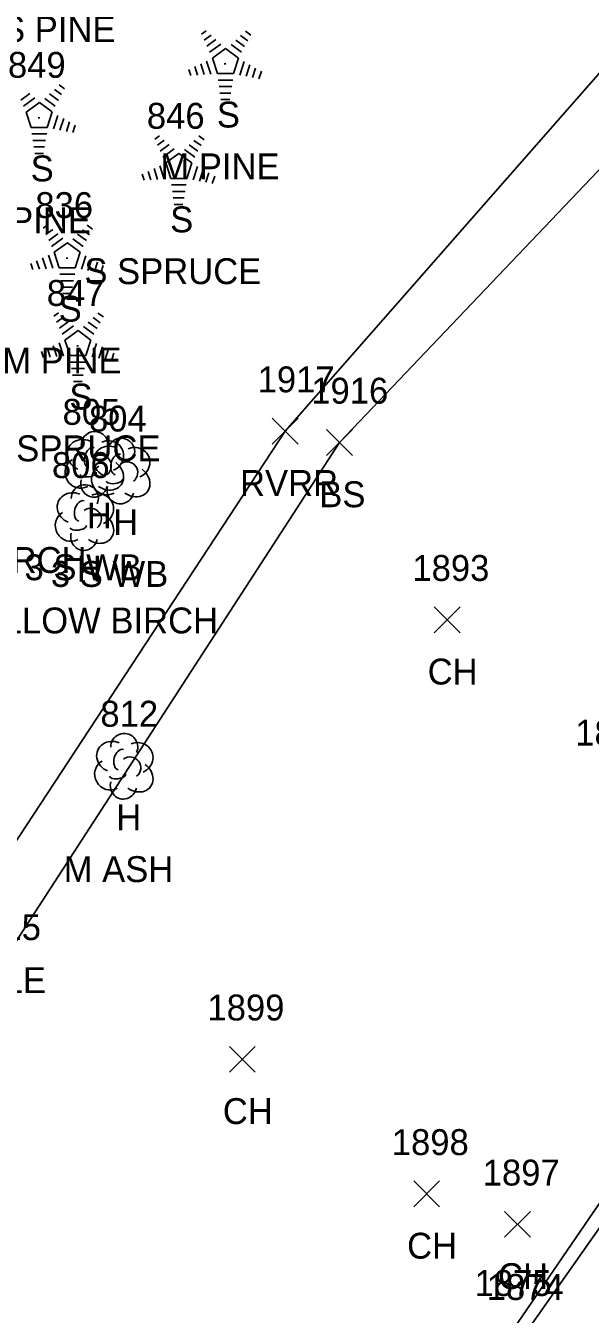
# Model space of a CAD drawing. Extents: x 1545627 to 1546562, y 571176 to 576667.
# Drawn here: x 1546167.5 to 1546211.1, y 572214.6 to 572314.1 of the extents above; entities that cross this region are included whole.
import ezdxf

# ---------------------------------------------------------------- set-up
doc = ezdxf.new("R2010")
doc.units = 0
for name, color, linetype in [('L_A', 7, 'Continuous'), ('L_C', 7, 'Continuous'), ('L_I', 7, 'Continuous'), ('L_TIC', 7, 'Continuous'), ('LAWE', 7, 'Continuous'), ('LELB', 7, 'Continuous'), ('LTC', 7, 'Continuous'), ('LTD', 7, 'Continuous')]:
    doc.layers.add(name, color=color, linetype=linetype)

msp = doc.modelspace()

# ---------------------------------------------------------------- linework, layer by layer
at = {"layer": 'L_TIC'}
for points in [[(1546186.565, 572281.786), (1546188.565, 572283.786)], [(1546188.565, 572281.786), (1546186.565, 572283.786)], [(1546190.763, 572280.913), (1546192.763, 572282.913)], [(1546192.763, 572280.913), (1546190.763, 572282.913)], [(1546199.088, 572267.221), (1546201.088, 572269.221)], [(1546201.088, 572267.221), (1546199.088, 572269.221)], [(1546183.26, 572233.275), (1546185.26, 572235.275)], [(1546185.26, 572233.275), (1546183.26, 572235.275)], [(1546197.499, 572222.88), (1546199.499, 572224.88)], [(1546199.499, 572222.88), (1546197.499, 572224.88)], [(1546204.526, 572220.528), (1546206.526, 572222.528)], [(1546206.526, 572220.528), (1546204.526, 572222.528)]]:
    msp.add_lwpolyline(points, dxfattribs=at)
at = {"layer": 'LAWE'}
for points in [[(1546079.438, 571966.947), (1546077.788, 571985.488), (1546075.176, 572034.738), (1546072.514, 572073.367), (1546072.957, 572091.545), (1546079.326, 572109.636), (1546089.965, 572133.875), (1546098.205, 572146.168), (1546103.269, 572146.803), (1546106.386, 572149.622), (1546130.143, 572181.263), (1546136.759, 572192.153), (1546140.729, 572200.768), (1546161.621, 572243.317), (1546187.565, 572282.786), (1546232.645, 572334.154), (1546255.297, 572360.235), (1546268.959, 572391.116)], [(1546121.265, 571957.172), (1546118.803, 571996.677), (1546114.937, 572038.101), (1546108, 572065.636), (1546104.767, 572084.584), (1546111.687, 572095.842), (1546118.703, 572113.935), (1546133.848, 572134.836), (1546145.167, 572135.646), (1546153.927, 572139.019), (1546169.651, 572160.036), (1546189.008, 572163.697), (1546206.714, 572193.958), (1546205.832, 572212.69), (1546216.066, 572227.226), (1546228.024, 572235.176), (1546234.868, 572265.766), (1546262.797, 572295.702), (1546275.487, 572309.557), (1546290.065, 572324.25)]]:
    msp.add_lwpolyline(points, dxfattribs=at)
at = {"layer": 'LELB'}
for points in [[(1546140.457, 572188.687), (1546144.086, 572197.302), (1546164.869, 572240.482), (1546191.763, 572281.913), (1546238.283, 572330.782), (1546258.38, 572354.309), (1546270.264, 572391.299)], [(1546138.465, 572142.662), (1546151.843, 572140.861), (1546169.324, 572161.725), (1546185.772, 572170.699), (1546202.895, 572194.936), (1546204.894, 572212.997), (1546215.164, 572227.989), (1546230.472, 572267.575), (1546260.052, 572296.387), (1546273.8, 572312.974), (1546290.068, 572327.618), (1546314.576, 572291.02)]]:
    msp.add_lwpolyline(points, dxfattribs=at)
at = {"layer": 'LTC'}
for p, q in [((1546181.096, 572313.446), (1546181.45, 572313.703)), ((1546184.494, 572313.686), (1546184.913, 572313.382)), ((1546181.305, 572312.98), (1546181.835, 572313.364)), ((1546181.515, 572312.514), (1546182.219, 572313.026)), ((1546181.725, 572312.049), (1546182.603, 572312.687)), ((1546183.381, 572312.641), (1546184.19, 572312.052)), ((1546183.752, 572312.989), (1546184.431, 572312.496)), ((1546184.123, 572313.338), (1546184.672, 572312.939)), ((1546181.949, 572311.594), (1546182.961, 572312.328)), ((1546181.949, 572311.594), (1546182.336, 572310.4)), ((1546182.961, 572312.328), (1546183.958, 572311.603)), ((1546183.958, 572311.603), (1546183.567, 572310.4)), ((1546180.128, 572310.725), (1546180.28, 572310.257)), ((1546180.584, 572310.942), (1546180.795, 572310.29)), ((1546181.039, 572311.158), (1546181.31, 572310.323)), ((1546181.495, 572311.374), (1546181.825, 572310.355)), ((1546184.395, 572311.332), (1546184.057, 572310.293)), ((1546184.84, 572311.082), (1546184.552, 572310.197)), ((1546185.285, 572310.832), (1546185.047, 572310.102)), ((1546185.729, 572310.582), (1546185.542, 572310.007)), ((1546170.106, 572309.526), (1546170.525, 572309.222)), ((1546183.567, 572310.4), (1546182.336, 572310.4)), ((1546183.528, 572309.9), (1546182.384, 572309.9)), ((1546167.127, 572308.354), (1546167.831, 572308.866)), ((1546167.337, 572307.889), (1546168.215, 572308.527)), ((1546169.364, 572308.829), (1546170.043, 572308.336)), ((1546169.735, 572309.178), (1546170.285, 572308.779)), ((1546183.445, 572309.4), (1546182.456, 572309.4)), ((1546183.361, 572308.9), (1546182.529, 572308.9)), ((1546167.561, 572307.434), (1546168.573, 572308.168)), ((1546168.573, 572308.168), (1546169.57, 572307.443)), ((1546168.993, 572308.481), (1546169.802, 572307.892)), ((1546183.277, 572308.4), (1546182.602, 572308.4)), ((1546167.561, 572307.434), (1546167.948, 572306.24)), ((1546169.57, 572307.443), (1546169.179, 572306.24)), ((1546170.007, 572307.172), (1546169.67, 572306.133)), ((1546170.452, 572306.922), (1546170.165, 572306.037)), ((1546170.897, 572306.672), (1546170.66, 572305.942)), ((1546169.179, 572306.24), (1546167.948, 572306.24)), ((1546169.14, 572305.74), (1546167.996, 572305.74)), ((1546171.341, 572306.422), (1546171.154, 572305.847)), ((1546177.489, 572305.35), (1546177.843, 572305.608)), ((1546180.887, 572305.591), (1546181.306, 572305.286)), ((1546169.057, 572305.24), (1546168.068, 572305.24)), ((1546168.973, 572304.74), (1546168.141, 572304.74)), ((1546177.698, 572304.885), (1546178.227, 572305.269)), ((1546177.908, 572304.419), (1546178.612, 572304.93)), ((1546178.117, 572303.953), (1546178.996, 572304.591)), ((1546179.774, 572304.546), (1546180.583, 572303.957)), ((1546180.145, 572304.894), (1546180.824, 572304.4)), ((1546180.516, 572305.242), (1546181.065, 572304.843)), ((1546168.889, 572304.24), (1546168.214, 572304.24)), ((1546178.342, 572303.498), (1546179.354, 572304.233)), ((1546179.354, 572304.233), (1546180.351, 572303.508)), ((1546176.521, 572302.63), (1546176.673, 572302.162)), ((1546176.977, 572302.846), (1546177.188, 572302.195)), ((1546177.432, 572303.063), (1546177.703, 572302.227)), ((1546177.887, 572303.279), (1546178.218, 572302.26)), ((1546178.342, 572303.498), (1546178.729, 572302.305)), ((1546180.351, 572303.508), (1546179.959, 572302.305)), ((1546180.788, 572303.237), (1546180.45, 572302.197)), ((1546181.233, 572302.987), (1546180.945, 572302.102)), ((1546181.677, 572302.737), (1546181.44, 572302.007)), ((1546179.959, 572302.305), (1546178.729, 572302.305)), ((1546179.921, 572301.805), (1546178.777, 572301.805)), ((1546182.122, 572302.486), (1546181.935, 572301.912)), ((1546179.837, 572301.305), (1546178.849, 572301.305)), ((1546179.754, 572300.805), (1546178.922, 572300.805)), ((1546179.67, 572300.305), (1546178.995, 572300.305)), ((1546168.873, 572298.453), (1546169.227, 572298.711)), ((1546172.271, 572298.694), (1546172.69, 572298.389)), ((1546169.082, 572297.988), (1546169.611, 572298.372)), ((1546169.292, 572297.522), (1546169.995, 572298.033)), ((1546169.501, 572297.056), (1546170.38, 572297.694)), ((1546171.157, 572297.649), (1546171.967, 572297.06)), ((1546171.529, 572297.997), (1546172.208, 572297.503)), ((1546171.9, 572298.345), (1546172.449, 572297.946)), ((1546169.726, 572296.601), (1546170.737, 572297.336)), ((1546169.726, 572296.601), (1546170.113, 572295.408)), ((1546170.737, 572297.336), (1546171.735, 572296.611)), ((1546171.735, 572296.611), (1546171.343, 572295.408)), ((1546167.905, 572295.732), (1546168.057, 572295.264)), ((1546168.36, 572295.949), (1546168.572, 572295.297)), ((1546168.816, 572296.166), (1546169.087, 572295.33)), ((1546169.271, 572296.382), (1546169.602, 572295.363)), ((1546172.172, 572296.34), (1546171.834, 572295.3)), ((1546172.617, 572296.089), (1546172.329, 572295.205)), ((1546173.061, 572295.839), (1546172.824, 572295.11)), ((1546173.505, 572295.589), (1546173.319, 572295.015)), ((1546171.343, 572295.408), (1546170.113, 572295.408)), ((1546171.305, 572294.908), (1546170.16, 572294.908)), ((1546171.221, 572294.408), (1546170.233, 572294.408)), ((1546171.137, 572293.908), (1546170.306, 572293.908)), ((1546171.054, 572293.408), (1546170.379, 572293.408)), ((1546169.699, 572291.669), (1546170.053, 572291.927)), ((1546173.097, 572291.91), (1546173.516, 572291.605)), ((1546169.908, 572291.204), (1546170.437, 572291.588)), ((1546170.118, 572290.738), (1546170.822, 572291.249)), ((1546170.327, 572290.272), (1546171.206, 572290.91)), ((1546171.984, 572290.865), (1546172.793, 572290.276)), ((1546172.355, 572291.213), (1546173.034, 572290.719)), ((1546172.726, 572291.562), (1546173.275, 572291.162)), ((1546170.552, 572289.817), (1546171.564, 572290.552)), ((1546170.552, 572289.817), (1546170.939, 572288.624)), ((1546171.564, 572290.552), (1546172.561, 572289.827)), ((1546172.561, 572289.827), (1546172.17, 572288.624)), ((1546168.731, 572288.949), (1546168.883, 572288.481)), ((1546169.187, 572289.165), (1546169.398, 572288.514)), ((1546169.642, 572289.382), (1546169.913, 572288.547)), ((1546170.097, 572289.598), (1546170.428, 572288.579)), ((1546172.17, 572288.624), (1546170.939, 572288.624)), ((1546172.998, 572289.556), (1546172.66, 572288.517)), ((1546173.443, 572289.306), (1546173.155, 572288.421)), ((1546173.887, 572289.056), (1546173.65, 572288.326)), ((1546174.332, 572288.805), (1546174.145, 572288.231)), ((1546172.131, 572288.124), (1546170.987, 572288.124)), ((1546172.047, 572287.624), (1546171.059, 572287.624)), ((1546171.964, 572287.124), (1546171.132, 572287.124)), ((1546171.88, 572286.624), (1546171.205, 572286.624))]:
    msp.add_line(p, q, dxfattribs=at)
at = {"layer": 'LTD'}
for p, q in [((1546172.805, 572280.277), (1546172.805, 572280.277)), ((1546172.805, 572280.277), (1546172.805, 572280.277)), ((1546174.843, 572279.759), (1546174.843, 572279.759)), ((1546174.843, 572279.759), (1546174.843, 572279.759)), ((1546172.037, 572276.167), (1546172.037, 572276.167)), ((1546172.037, 572276.167), (1546172.037, 572276.167)), ((1546175.082, 572256.963), (1546175.082, 572256.963)), ((1546175.082, 572256.963), (1546175.082, 572256.963))]:
    msp.add_line(p, q, dxfattribs=at)
for centre in [(1546172.852, 572281.711), (1546174.89, 572281.193), (1546172.084, 572277.601), (1546175.129, 572258.397)]:
    msp.add_arc(centre, 1.047, 335.52715, 180.95627, dxfattribs=at)
for centre, major_axis, ratio, start_param, end_param in [((1546172.013, 572280.943), (1.21, -0.512), 0.895232, 1.570796, 4.712389), ((1546174.051, 572280.426), (1.21, -0.512), 0.895232, 1.570796, 4.712389), ((1546173.847, 572280.86), (-1.141, -0.483), 0.949671, 1.570796, 4.712389), ((1546175.885, 572280.343), (-1.141, -0.483), 0.949671, 1.570796, 4.712389), ((1546172.597, 572280.735), (-0.208, -0.792), 0.645439, 3.141593, 6.283185), ((1546173.305, 572280.11), (-0.5, 0.667), 0.989748, 3.141593, 6.283185), ((1546174.635, 572280.218), (-0.208, -0.792), 0.645439, 3.141593, 6.283185), ((1546171.722, 572279.568), (0.584, -1.042), 0.959034, 3.141593, 6.283185), ((1546173.76, 572279.051), (0.584, -1.042), 0.959034, 3.141593, 6.283185), ((1546173.805, 572279.443), (-1.09, 0.792), 0.841452, 1.570796, 4.712389), ((1546175.343, 572279.593), (-0.5, 0.667), 0.989748, 3.141593, 6.283185), ((1546175.843, 572278.926), (-1.09, 0.792), 0.841452, 1.570796, 4.712389), ((1546172.806, 572278.777), (0.265, 1.061), 0.942809, 1.570796, 4.712389), ((1546172.347, 572279.526), (-0.625, -0.083), 0.423636, 0, 3.141593), ((1546174.385, 572279.009), (-0.625, -0.083), 0.423636, 0, 3.141593), ((1546171.245, 572276.834), (1.21, -0.512), 0.895232, 1.570796, 4.712389), ((1546173.078, 572276.751), (-1.141, -0.483), 0.949671, 1.570796, 4.712389), ((1546174.843, 572278.26), (0.265, 1.061), 0.942809, 1.570796, 4.712389), ((1546171.828, 572276.625), (-0.208, -0.792), 0.645439, 3.141593, 6.283185), ((1546172.537, 572276), (-0.5, 0.667), 0.989748, 3.141593, 6.283185), ((1546170.954, 572275.459), (0.584, -1.042), 0.959034, 3.141593, 6.283185), ((1546173.037, 572275.334), (-1.09, 0.792), 0.841452, 1.570796, 4.712389), ((1546172.037, 572274.667), (0.265, 1.061), 0.942809, 1.570796, 4.712389), ((1546171.579, 572275.417), (-0.625, -0.083), 0.423636, 0, 3.141593), ((1546174.29, 572257.63), (1.21, -0.512), 0.895232, 1.570796, 4.712389), ((1546176.124, 572257.547), (-1.141, -0.483), 0.949671, 1.570796, 4.712389), ((1546174.874, 572257.421), (-0.208, -0.792), 0.645439, 3.141593, 6.283185), ((1546173.999, 572256.255), (0.584, -1.042), 0.959034, 3.141593, 6.283185), ((1546175.582, 572256.797), (-0.5, 0.667), 0.989748, 3.141593, 6.283185), ((1546176.082, 572256.13), (-1.09, 0.792), 0.841452, 1.570796, 4.712389), ((1546174.624, 572256.213), (-0.625, -0.083), 0.423636, 0, 3.141593), ((1546175.082, 572255.463), (0.265, 1.061), 0.942809, 1.570796, 4.712389)]:
    msp.add_ellipse(centre, major_axis=major_axis, ratio=ratio, start_param=start_param, end_param=end_param, dxfattribs=at)

# ---------------------------------------------------------------- texts
at = {"layer": 'L_A'}
for s, p in [('S', (1546182.286, 572306.238)), ('S', (1546167.899, 572302.078)), ('S', (1546178.679, 572298.142)), ('S', (1546170.063, 572291.245)), ('S', (1546170.889, 572284.461)), ('RVRR', (1546184.077, 572277.786)), ('BS', (1546190.204, 572276.913)), ('H', (1546172.238, 572275.277)), ('H', (1546174.276, 572274.759)), ('H', (1546171.47, 572271.167)), ('CH', (1546198.577, 572263.221)), ('H', (1546174.515, 572251.963)), ('CH', (1546182.748, 572229.275)), ('CH', (1546196.987, 572218.88)), ('CH', (1546204.014, 572216.528))]:
    msp.add_text(s, height=2, dxfattribs=at).set_placement(p)
at = {"layer": 'L_C'}
for s, p in [('S PINE', (1546165.686, 572312.832)), ('M PINE', (1546177.924, 572302.238)), ('S PINE', (1546163.788, 572298.078)), ('S SPRUCE', (1546172.049, 572294.142)), ('M PINE', (1546165.701, 572287.245)), ('S SPRUCE', (1546164.259, 572280.461)), ('S YELLOW BIRCH', (1546149.482, 572271.837)), ('3 S WB', (1546167.427, 572271.277)), ('3 S WB', (1546169.465, 572270.759)), ('S YELLOW BIRCH', (1546159.643, 572267.167)), ('M ASH', (1546170.452, 572247.963)), ('3 S MAPLE', (1546155.259, 572239.386))]:
    msp.add_text(s, height=2, dxfattribs=at).set_placement(p)
at = {"layer": 'L_I'}
for s, p in [('849', (1546166.143, 572310.078)), ('846', (1546176.876, 572306.142)), ('836', (1546168.26, 572299.245)), ('847', (1546169.141, 572292.461)), ('1917', (1546185.439, 572285.786)), ('1916', (1546189.582, 572284.913)), ('805', (1546170.364, 572283.277)), ('804', (1546172.402, 572282.759)), ('806', (1546169.541, 572279.167)), ('1893', (1546197.396, 572271.221)), ('812', (1546173.287, 572259.963)), ('1894', (1546209.983, 572258.5)), ('1915', (1546162.743, 572243.482)), ('1899', (1546181.56, 572237.275)), ('1898', (1546195.806, 572226.88)), ('1897', (1546202.833, 572224.528)), ('1875', (1546202.201, 572215.997)), ('1874', (1546203.14, 572215.69))]:
    msp.add_text(s, height=2, dxfattribs=at).set_placement(p)
at = {"layer": 'LTC'}
for p in [(1546182.843, 572311.342), (1546168.455, 572307.182), (1546179.236, 572303.246), (1546170.62, 572296.349), (1546171.446, 572289.565)]:
    msp.add_text('.', height=1.037, rotation=270, dxfattribs=at).set_placement(p)

doc.saveas('drawing.dxf')
